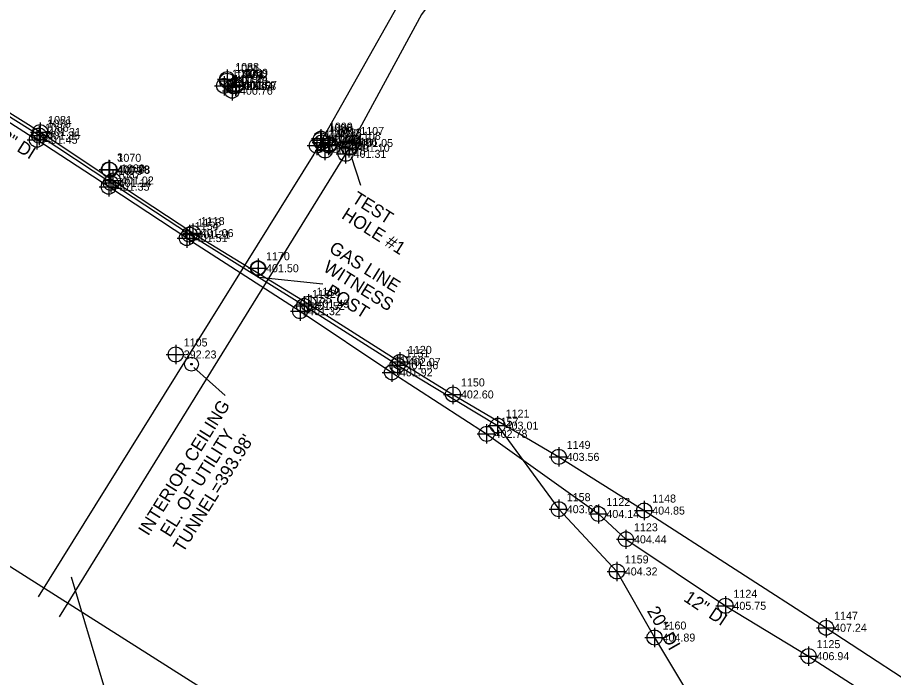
# Model space of a CAD drawing. Extents: x 2024146 to 2025516, y 819906 to 820765.
# Drawn here: x 2024645.2 to 2024918.9, y 820314.8 to 820520.8 of the extents above; entities that cross this region are included whole.
import ezdxf

# ---------------------------------------------------------------- set-up
doc = ezdxf.new("R2010")
doc.units = 0
for name, color, linetype in [('Exist Vertical Profile Horizontal Axis Label Major', 7, 'Continuous'), ('Exist Vertical Profile Vertical Axis Label', 7, 'Continuous'), ('Prop Lane Lines', 7, 'Continuous'), ('Sheet Block Revision CELL', 7, 'Continuous'), ('Sheet Block System Information CELL', 7, 'Continuous'), ('Sheet Data Field CELL', 7, 'Continuous'), ('Sheet DOT Grid CELL', 7, 'Continuous'), ('Sheet Layout Plan Border', 7, 'Continuous'), ('Sheet Layout Profile Border Port 2', 7, 'Continuous'), ('Sheet Plan And Profile CELL', 7, 'Continuous'), ('Sheet Plot Border Inside CELL', 7, 'Continuous'), ('Sheet Plot Border Outside CELL', 7, 'Continuous'), ('Sheet Profile Grid Minor CELL', 7, 'Continuous'), ('Sheet Sticker Incomplete CELL', 7, 'Continuous')]:
    doc.layers.add(name, color=color, linetype=linetype)

# ---------------------------------------------------------------- blocks, each defined once
blk = doc.blocks.new('EXIST OTHER CULTURE LOCATED OBJECT')
at = {"layer": 'Sheet DOT Grid CELL'}
for radius in [0.0436, 0.0048]:
    blk.add_circle((0, 0), radius, dxfattribs=at)
blk = doc.blocks.new('EXIST UTILITIES OTHER LOCATED OBJECT')
at = {"layer": 'Sheet Block System Information CELL'}
for radius in [0.0436, 0.0048]:
    blk.add_circle((0, 0), radius, dxfattribs=at)

msp = doc.modelspace()

# ---------------------------------------------------------------- linework, layer by layer
at = {"layer": 'Exist Vertical Profile Horizontal Axis Label Major'}
for points in [[(2024749.51, 820477.44), (2024752.34, 820468.45)], [(2024720.67, 820439.73), (2024740.6, 820437.65)]]:
    msp.add_lwpolyline(points, dxfattribs=at)
at = {"layer": 'Prop Lane Lines'}
msp.add_lwpolyline([(2024566.33, 820397.9), (2024753.12, 820279.6), (2025069.15, 820077.77), (2025141.71, 820076.11)], dxfattribs=at)
at = {"layer": 'Sheet Layout Plan Border'}
for points in [[(2024710.73, 820504.64), (2024710.73, 820501.64)], [(2024709.74, 820502.53), (2024709.74, 820499.53)], [(2024710.71, 820504.09), (2024710.71, 820501.09)], [(2024712.42, 820502.45), (2024712.42, 820499.45)], [(2024713.28, 820502.42), (2024713.28, 820499.42)], [(2024713.53, 820502.82), (2024713.53, 820499.82)], [(2024706.74, 820499.53), (2024709.74, 820499.53)], [(2024707.71, 820501.09), (2024710.71, 820501.09)], [(2024707.73, 820501.64), (2024710.73, 820501.64)], [(2024709.42, 820499.45), (2024712.42, 820499.45)], [(2024709.74, 820499.53), (2024712.74, 820499.53)], [(2024709.74, 820499.53), (2024709.74, 820496.53)], [(2024710.28, 820499.42), (2024713.28, 820499.42)], [(2024710.53, 820499.82), (2024713.53, 820499.82)], [(2024710.71, 820501.09), (2024713.71, 820501.09)], [(2024710.71, 820501.09), (2024710.71, 820498.09)], [(2024710.73, 820501.64), (2024713.73, 820501.64)], [(2024710.73, 820501.64), (2024710.73, 820498.64)], [(2024712.23, 820500.98), (2024712.23, 820497.98)], [(2024712.42, 820499.45), (2024715.42, 820499.45)], [(2024712.42, 820499.45), (2024712.42, 820496.45)], [(2024713.28, 820499.42), (2024716.28, 820499.42)], [(2024713.28, 820499.42), (2024713.28, 820496.42)], [(2024713.53, 820499.82), (2024716.53, 820499.82)], [(2024713.53, 820499.82), (2024713.53, 820496.82)], [(2024709.23, 820497.98), (2024712.23, 820497.98)], [(2024712.23, 820497.98), (2024715.23, 820497.98)], [(2024712.23, 820497.98), (2024712.23, 820494.98)], [(2024652.27, 820488.09), (2024652.27, 820485.09)], [(2024651.26, 820485.68), (2024651.26, 820482.68)], [(2024651.95, 820486.99), (2024651.95, 820483.99)], [(2024739.83, 820485.55), (2024739.83, 820482.55)], [(2024740.02, 820486.02), (2024740.02, 820483.02)], [(2024648.26, 820482.68), (2024651.26, 820482.68)], [(2024648.95, 820483.99), (2024651.95, 820483.99)], [(2024649.27, 820485.09), (2024652.27, 820485.09)], [(2024651.26, 820482.68), (2024654.26, 820482.68)], [(2024651.26, 820482.68), (2024651.26, 820479.68)], [(2024651.95, 820483.99), (2024654.95, 820483.99)], [(2024651.95, 820483.99), (2024651.95, 820480.99)], [(2024652.27, 820485.09), (2024655.27, 820485.09)], [(2024652.27, 820485.09), (2024652.27, 820482.09)], [(2024737.02, 820483.02), (2024740.02, 820483.02)], [(2024738.72, 820483.84), (2024738.72, 820480.84)], [(2024740.02, 820483.02), (2024743.02, 820483.02)], [(2024740.02, 820483.02), (2024740.02, 820480.02)], [(2024740.24, 820484.84), (2024740.24, 820481.84)], [(2024742.33, 820483.91), (2024742.33, 820480.91)], [(2024742.84, 820484.17), (2024742.84, 820481.17)], [(2024748.76, 820483.16), (2024748.76, 820480.16)], [(2024749.82, 820484.67), (2024749.82, 820481.67)], [(2024735.72, 820480.84), (2024738.72, 820480.84)], [(2024736.83, 820482.55), (2024739.83, 820482.55)], [(2024737.24, 820481.84), (2024740.24, 820481.84)], [(2024738.72, 820480.84), (2024741.72, 820480.84)], [(2024738.72, 820480.84), (2024738.72, 820477.84)], [(2024739.33, 820480.91), (2024742.33, 820480.91)], [(2024739.83, 820482.55), (2024742.83, 820482.55)], [(2024739.83, 820482.55), (2024739.83, 820479.55)], [(2024739.84, 820481.17), (2024742.84, 820481.17)], [(2024740.24, 820481.84), (2024743.24, 820481.84)], [(2024740.24, 820481.84), (2024740.24, 820478.84)], [(2024741.26, 820482.33), (2024741.26, 820479.33)], [(2024742.33, 820480.91), (2024745.33, 820480.91)], [(2024742.33, 820480.91), (2024742.33, 820477.91)], [(2024742.84, 820481.17), (2024745.84, 820481.17)], [(2024742.84, 820481.17), (2024742.84, 820478.17)], [(2024745.76, 820480.16), (2024748.76, 820480.16)], [(2024746.82, 820481.67), (2024749.82, 820481.67)], [(2024747.73, 820481.28), (2024747.73, 820478.28)], [(2024748.76, 820480.16), (2024751.76, 820480.16)], [(2024748.76, 820480.16), (2024748.76, 820477.16)], [(2024749.82, 820481.67), (2024752.82, 820481.67)], [(2024749.82, 820481.67), (2024749.82, 820478.67)], [(2024738.26, 820479.33), (2024741.26, 820479.33)], [(2024741.26, 820479.33), (2024744.26, 820479.33)], [(2024741.26, 820479.33), (2024741.26, 820476.33)], [(2024744.73, 820478.28), (2024747.73, 820478.28)], [(2024747.73, 820478.28), (2024750.73, 820478.28)], [(2024747.73, 820478.28), (2024747.73, 820475.28)], [(2024673.77, 820476.41), (2024673.77, 820473.41)], [(2024673.93, 820476.29), (2024673.93, 820473.29)], [(2024670.77, 820473.41), (2024673.77, 820473.41)], [(2024670.93, 820473.29), (2024673.93, 820473.29)], [(2024673.77, 820473.41), (2024676.77, 820473.41)], [(2024673.77, 820473.41), (2024673.77, 820470.41)], [(2024673.93, 820473.29), (2024676.93, 820473.29)], [(2024673.93, 820473.29), (2024673.93, 820470.29)], [(2024674.33, 820472.18), (2024674.33, 820469.18)], [(2024675.04, 820472.96), (2024675.04, 820469.96)], [(2024671.33, 820469.18), (2024674.33, 820469.18)], [(2024672.04, 820469.96), (2024675.04, 820469.96)], [(2024673.72, 820471.01), (2024673.72, 820468.01)], [(2024674.33, 820469.18), (2024677.33, 820469.18)], [(2024674.33, 820469.18), (2024674.33, 820466.18)], [(2024675.04, 820469.96), (2024678.04, 820469.96)], [(2024675.04, 820469.96), (2024675.04, 820466.96)], [(2024670.72, 820468.01), (2024673.72, 820468.01)], [(2024673.72, 820468.01), (2024676.72, 820468.01)], [(2024673.72, 820468.01), (2024673.72, 820465.01)], [(2024698.94, 820456.07), (2024698.94, 820453.07)], [(2024699.98, 820456.54), (2024699.98, 820453.54)], [(2024695.94, 820453.07), (2024698.94, 820453.07)], [(2024696.98, 820453.54), (2024699.98, 820453.54)], [(2024698.1, 820454.98), (2024698.1, 820451.98)], [(2024698.94, 820453.07), (2024701.94, 820453.07)], [(2024698.94, 820453.07), (2024698.94, 820450.07)], [(2024699.98, 820453.54), (2024702.98, 820453.54)], [(2024699.98, 820453.54), (2024699.98, 820450.54)], [(2024695.1, 820451.98), (2024698.1, 820451.98)], [(2024698.1, 820451.98), (2024701.1, 820451.98)], [(2024698.1, 820451.98), (2024698.1, 820448.98)], [(2024720.36, 820445.56), (2024720.36, 820442.56)], [(2024717.36, 820442.56), (2024720.36, 820442.56)], [(2024720.36, 820442.56), (2024723.36, 820442.56)], [(2024720.36, 820442.56), (2024720.36, 820439.56)], [(2024734.74, 820433.8), (2024734.74, 820430.8)], [(2024736.13, 820434.49), (2024736.13, 820431.49)], [(2024731.74, 820430.8), (2024734.74, 820430.8)], [(2024733.13, 820431.49), (2024736.13, 820431.49)], [(2024733.5, 820432.16), (2024733.5, 820429.16)], [(2024734.74, 820430.8), (2024737.74, 820430.8)], [(2024734.74, 820430.8), (2024734.74, 820427.8)], [(2024736.13, 820431.49), (2024739.13, 820431.49)], [(2024736.13, 820431.49), (2024736.13, 820428.49)], [(2024730.5, 820429.16), (2024733.5, 820429.16)], [(2024733.5, 820429.16), (2024736.5, 820429.16)], [(2024733.5, 820429.16), (2024733.5, 820426.16)], [(2024694.65, 820418.64), (2024694.65, 820415.64)], [(2024691.65, 820415.64), (2024694.65, 820415.64)], [(2024694.65, 820415.64), (2024697.65, 820415.64)], [(2024694.65, 820415.64), (2024694.65, 820412.64)], [(2024763.96, 820415.28), (2024763.96, 820412.28)], [(2024764.7, 820416.32), (2024764.7, 820413.32)], [(2024760.96, 820412.28), (2024763.96, 820412.28)], [(2024761.7, 820413.32), (2024764.7, 820413.32)], [(2024762.19, 820413.06), (2024762.19, 820410.06)], [(2024763.96, 820412.28), (2024766.96, 820412.28)], [(2024763.96, 820412.28), (2024763.96, 820409.28)], [(2024764.7, 820413.32), (2024767.7, 820413.32)], [(2024764.7, 820413.32), (2024764.7, 820410.32)], [(2024759.19, 820410.06), (2024762.19, 820410.06)], [(2024762.19, 820410.06), (2024765.19, 820410.06)], [(2024762.19, 820410.06), (2024762.19, 820407.06)], [(2024781.27, 820406.16), (2024781.27, 820403.16)], [(2024778.27, 820403.16), (2024781.27, 820403.16)], [(2024781.27, 820403.16), (2024784.27, 820403.16)], [(2024781.27, 820403.16), (2024781.27, 820400.16)], [(2024795.23, 820396.42), (2024795.23, 820393.42)], [(2024791.8, 820393.86), (2024791.8, 820390.86)], [(2024792.23, 820393.42), (2024795.23, 820393.42)], [(2024795.23, 820393.42), (2024798.23, 820393.42)], [(2024795.23, 820393.42), (2024795.23, 820390.42)], [(2024788.8, 820390.86), (2024791.8, 820390.86)], [(2024791.8, 820390.86), (2024794.8, 820390.86)], [(2024791.8, 820390.86), (2024791.8, 820387.86)], [(2024814.31, 820386.67), (2024814.31, 820383.67)], [(2024811.31, 820383.67), (2024814.31, 820383.67)], [(2024814.31, 820383.67), (2024817.31, 820383.67)], [(2024814.31, 820383.67), (2024814.31, 820380.67)], [(2024814.33, 820370.34), (2024814.33, 820367.34)], [(2024826.71, 820368.84), (2024826.71, 820365.84)], [(2024841.03, 820369.91), (2024841.03, 820366.91)], [(2024811.33, 820367.34), (2024814.33, 820367.34)], [(2024814.33, 820367.34), (2024817.33, 820367.34)], [(2024814.33, 820367.34), (2024814.33, 820364.34)], [(2024823.71, 820365.84), (2024826.71, 820365.84)], [(2024826.71, 820365.84), (2024829.71, 820365.84)], [(2024826.71, 820365.84), (2024826.71, 820362.84)], [(2024838.03, 820366.91), (2024841.03, 820366.91)], [(2024841.03, 820366.91), (2024844.03, 820366.91)], [(2024841.03, 820366.91), (2024841.03, 820363.91)], [(2024835.33, 820360.93), (2024835.33, 820357.93)], [(2024832.33, 820357.93), (2024835.33, 820357.93)], [(2024835.33, 820357.93), (2024838.33, 820357.93)], [(2024835.33, 820357.93), (2024835.33, 820354.93)], [(2024832.46, 820350.9), (2024832.46, 820347.9)], [(2024829.46, 820347.9), (2024832.46, 820347.9)], [(2024832.46, 820347.9), (2024835.46, 820347.9)], [(2024832.46, 820347.9), (2024832.46, 820344.9)], [(2024866.41, 820340.18), (2024866.41, 820337.18)], [(2024863.41, 820337.18), (2024866.41, 820337.18)], [(2024866.41, 820337.18), (2024869.41, 820337.18)], [(2024866.41, 820337.18), (2024866.41, 820334.18)], [(2024897.86, 820333.32), (2024897.86, 820330.32)], [(2024844.26, 820330.26), (2024844.26, 820327.26)], [(2024894.86, 820330.32), (2024897.86, 820330.32)], [(2024897.86, 820330.32), (2024900.86, 820330.32)], [(2024897.86, 820330.32), (2024897.86, 820327.32)], [(2024841.26, 820327.26), (2024844.26, 820327.26)], [(2024844.26, 820327.26), (2024847.26, 820327.26)], [(2024844.26, 820327.26), (2024844.26, 820324.26)], [(2024892.38, 820324.46), (2024892.38, 820321.46)], [(2024889.38, 820321.46), (2024892.38, 820321.46)], [(2024892.38, 820321.46), (2024895.38, 820321.46)], [(2024892.38, 820321.46), (2024892.38, 820318.46)]]:
    msp.add_lwpolyline(points, dxfattribs=at)
for centre in [(2024709.74, 820499.53), (2024710.71, 820501.09), (2024710.73, 820501.64), (2024712.42, 820499.45), (2024713.28, 820499.42), (2024713.53, 820499.82), (2024712.23, 820497.98), (2024651.95, 820483.99), (2024652.27, 820485.09), (2024740.02, 820483.02), (2024651.26, 820482.68), (2024738.72, 820480.84), (2024739.83, 820482.55), (2024740.24, 820481.84), (2024742.33, 820480.91), (2024742.84, 820481.17), (2024749.82, 820481.67), (2024741.26, 820479.33), (2024747.73, 820478.28), (2024748.76, 820480.16), (2024673.77, 820473.41), (2024673.93, 820473.29), (2024675.04, 820469.96), (2024673.72, 820468.01), (2024674.33, 820469.18), (2024698.94, 820453.07), (2024699.98, 820453.54), (2024698.1, 820451.98), (2024720.36, 820442.56), (2024736.13, 820431.49), (2024733.5, 820429.16), (2024734.74, 820430.8), (2024694.65, 820415.64), (2024763.96, 820412.28), (2024764.7, 820413.32), (2024762.19, 820410.06), (2024781.27, 820403.16), (2024795.23, 820393.42), (2024791.8, 820390.86), (2024814.31, 820383.67), (2024814.33, 820367.34), (2024826.71, 820365.84), (2024841.03, 820366.91), (2024835.33, 820357.93), (2024832.46, 820347.9), (2024866.41, 820337.18), (2024897.86, 820330.32), (2024844.26, 820327.26), (2024892.38, 820321.46)]:
    msp.add_circle(centre, 2.34, dxfattribs=at)
at = {"layer": 'Sheet Plan And Profile CELL'}
for points in [[(2024559.18, 820542.37), (2024594.35, 820519.69), (2024613.47, 820506.78), (2024651.26, 820482.68)], [(2024698.94, 820453.07), (2024674.33, 820469.18), (2024651.95, 820483.99), (2024627.17, 820499.52), (2024614.79, 820508.68), (2024602.02, 820517.3), (2024599.33, 820518.11), (2024580.9, 820516.52)], [(2024698.1, 820451.98), (2024673.72, 820468.01), (2024651.26, 820482.68)], [(2024763.96, 820412.28), (2024734.74, 820430.8), (2024698.94, 820453.07)], [(2024698.1, 820451.98), (2024733.5, 820429.16), (2024762.19, 820410.06), (2024791.8, 820390.86), (2024826.71, 820365.84)], [(2024763.96, 820412.28), (2024795.23, 820393.42)], [(2024795.23, 820393.42), (2024814.33, 820367.34)], [(2024814.33, 820367.34), (2024832.46, 820347.9), (2024844.26, 820327.26), (2024863.2, 820295.75), (2024898.76, 820266.45), (2024929.96, 820244.34), (2024954.97, 820224.61), (2024992.58, 820197.53)], [(2024826.71, 820365.84), (2024835.33, 820357.93), (2024866.41, 820337.18), (2024892.38, 820321.46), (2024924.16, 820301.03), (2024946.59, 820287.22), (2024967.06, 820274.36), (2024988.57, 820261.62), (2025010.79, 820248.47), (2025045.82, 820229.11), (2025063.46, 820215.95), (2025102.86, 820187.61), (2025131, 820170.89), (2025157.73, 820152.25), (2025180.55, 820137.37)]]:
    msp.add_lwpolyline(points, dxfattribs=at)
at = {"layer": 'Sheet Plot Border Inside CELL'}
for points in [[(2024700.26, 820411.55), (2024710.11, 820402.81)], [(2024662, 820346.17), (2024676.28, 820298.43)]]:
    msp.add_lwpolyline(points, dxfattribs=at)
at = {"layer": 'Sheet Profile Grid Minor CELL'}
for points in [[(2024699.98, 820453.54), (2024675.04, 820469.96), (2024652.27, 820485.09), (2024627.61, 820500.49)], [(2024699.98, 820453.54), (2024736.13, 820431.49), (2024764.7, 820413.32), (2024781.27, 820403.16)], [(2024781.27, 820403.16), (2024814.31, 820383.67), (2024841.03, 820366.91), (2024897.86, 820330.32), (2024934.85, 820306.1), (2024972.48, 820282.87), (2024995.25, 820268.99), (2025029.71, 820246.26), (2025066.92, 820223.12), (2025091.61, 820207.05), (2025109.4, 820196), (2025136.22, 820178.55), (2025163.27, 820161.2)]]:
    msp.add_lwpolyline(points, dxfattribs=at)
at = {"layer": 'Sheet Sticker Incomplete CELL'}
msp.add_line((2024748.78, 820479.97), (2024658.17, 820333.7), dxfattribs=at)
for points in [[(2024799.19, 820558.91), (2024771.48, 820521.75), (2024748.78, 820479.97)], [(2024765.08, 820526.55), (2024737.81, 820478.22), (2024651.62, 820339.93)]]:
    msp.add_lwpolyline(points, dxfattribs=at)

# ---------------------------------------------------------------- block references
at = {"layer": 'Sheet Block System Information CELL', "xscale": 50, "yscale": 50}
for p in [(2024748.78, 820479.97), (2024720.36, 820442.56)]:
    msp.add_blockref('EXIST UTILITIES OTHER LOCATED OBJECT', p, dxfattribs=at)
at = {"layer": 'Sheet DOT Grid CELL', "xscale": 50, "yscale": 50}
msp.add_blockref('EXIST OTHER CULTURE LOCATED OBJECT', (2024699.58, 820412.6), dxfattribs=at)

# ---------------------------------------------------------------- texts
at = {"layer": 'Exist Vertical Profile Vertical Axis Label'}
for s, rotation, p in [('TEST', 327.6834, (2024749.39, 820463.4)), ('HOLE #1', 327.6834, (2024746.18, 820458.33)), ('GAS LINE', 328.063, (2024742.24, 820447.84)), ('WITNESS', 328.063, (2024740.44, 820441.89)), ('POST', 328.063, (2024741.12, 820434.4))]:
    msp.add_text(s, height=4, rotation=rotation, dxfattribs=at).set_placement(p)
at = {"layer": 'Sheet Block Revision CELL'}
for s, p in [('1092', (2024712.24, 820502.03)), ('1091', (2024713.21, 820503.59)), ('1088', (2024713.23, 820504.14)), ('1089', (2024716.03, 820502.32)), ('1093', (2024714.73, 820500.48)), ('1101', (2024714.92, 820501.95)), ('1090', (2024715.78, 820501.92)), ('1078', (2024654.45, 820486.49)), ('1081', (2024654.77, 820487.59)), ('1086', (2024653.76, 820485.18)), ('1095', (2024741.22, 820483.34)), ('1096', (2024742.33, 820485.05)), ('1099', (2024742.52, 820485.52)), ('1100', (2024742.74, 820484.34)), ('1097', (2024744.83, 820483.41)), ('1098', (2024745.34, 820483.67)), ('1107', (2024752.32, 820484.17)), ('1094', (2024743.76, 820481.83)), ('1106', (2024750.23, 820480.78)), ('1108', (2024751.26, 820482.66)), ('3', (2024676.27, 820475.91)), ('1070', (2024676.43, 820475.79)), ('1080', (2024677.54, 820472.46)), ('1087', (2024676.22, 820470.51)), ('1079', (2024676.83, 820471.68)), ('1153', (2024701.44, 820455.57)), ('1118', (2024702.48, 820456.04)), ('1154', (2024700.6, 820454.48)), ('1170', (2024722.86, 820445.06)), ('1119', (2024738.63, 820433.99)), ('1155', (2024736, 820431.66)), ('1152', (2024737.24, 820433.3)), ('1105', (2024697.15, 820418.14)), ('1151', (2024766.46, 820414.78)), ('1120', (2024767.2, 820415.82)), ('1156', (2024764.69, 820412.56)), ('1150', (2024783.77, 820405.66)), ('1121', (2024797.73, 820395.92)), ('1157', (2024794.3, 820393.36)), ('1149', (2024816.81, 820386.17)), ('1158', (2024816.83, 820369.84)), ('1122', (2024829.21, 820368.34)), ('1148', (2024843.53, 820369.41)), ('1123', (2024837.83, 820360.43)), ('1159', (2024834.96, 820350.4)), ('1124', (2024868.91, 820339.68)), ('1147', (2024900.36, 820332.82)), ('1160', (2024846.76, 820329.76)), ('1125', (2024894.88, 820323.96))]:
    msp.add_text(s, height=2.5, dxfattribs=at).set_placement(p)
at = {"layer": 'Sheet Data Field CELL'}
for s, rotation, p in [('12" DI', 327.9136, (2024636.82, 820484.23)), ('12" DI', 326.2747, (2024853.06, 820338.87)), ('20" DI', 299.7709, (2024841.79, 820335.62))]:
    msp.add_text(s, height=4, rotation=rotation, dxfattribs=at).set_placement(p)
at = {"layer": 'Sheet Layout Profile Border Port 2'}
for s, p in [('400.43', (2024713.21, 820499.84)), ('400.74', (2024713.23, 820500.39)), ('400.63', (2024712.24, 820498.28)), ('400.76', (2024714.73, 820496.73)), ('398.04', (2024714.92, 820498.2)), ('400.58', (2024715.78, 820498.17)), ('401.07', (2024716.03, 820498.57)), ('401.31', (2024654.77, 820483.84)), ('401.45', (2024653.76, 820481.43)), ('401.35', (2024654.45, 820482.74)), ('400.64', (2024742.33, 820481.3)), ('401.12', (2024742.52, 820481.77)), ('398.74', (2024742.74, 820480.59)), ('401.05', (2024752.32, 820480.42)), ('400.78', (2024741.22, 820479.59)), ('400.78', (2024743.76, 820478.08)), ('400.63', (2024744.83, 820479.66)), ('401.17', (2024745.34, 820479.92)), ('401.10', (2024751.26, 820478.91)), ('401.31', (2024750.23, 820477.03)), ('400.78', (2024676.27, 820472.16)), ('400.88', (2024676.43, 820472.04)), ('401.35', (2024676.22, 820466.76)), ('401.14', (2024676.83, 820467.93)), ('401.02', (2024677.54, 820468.71)), ('401.51', (2024700.6, 820450.73)), ('401.21', (2024701.44, 820451.82)), ('401.06', (2024702.48, 820452.29)), ('401.50', (2024722.86, 820441.31)), ('401.52', (2024737.24, 820429.55)), ('401.49', (2024738.63, 820430.24)), ('401.32', (2024736, 820427.91)), ('392.23', (2024697.15, 820414.39)), ('402.07', (2024767.2, 820412.07)), ('401.96', (2024766.46, 820411.03)), ('401.92', (2024764.69, 820408.81)), ('402.60', (2024783.77, 820401.91)), ('403.01', (2024797.73, 820392.17)), ('402.78', (2024794.3, 820389.61)), ('403.56', (2024816.81, 820382.42)), ('403.60', (2024816.83, 820366.09)), ('404.85', (2024843.53, 820365.66)), ('404.14', (2024829.21, 820364.59)), ('404.44', (2024837.83, 820356.68)), ('404.32', (2024834.96, 820346.65)), ('405.75', (2024868.91, 820335.93)), ('407.24', (2024900.36, 820329.07)), ('404.89', (2024846.76, 820326.01)), ('406.94', (2024894.88, 820320.21))]:
    msp.add_text(s, height=2.5, dxfattribs=at).set_placement(p)
at = {"layer": 'Sheet Plot Border Outside CELL'}
for s, p in [('INTERIOR CEILING ', (2024686.06, 820358.79)), ('EL. OF UTILITY ', (2024692.85, 820358.33)), ("TUNNEL=393.98'", (2024696.95, 820353.57))]:
    msp.add_text(s, height=4, rotation=57.9457, dxfattribs=at).set_placement(p)

doc.saveas('drawing.dxf')
